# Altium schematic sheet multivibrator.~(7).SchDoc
size 431 x 279 mm; SheetNumber: 1; SheetTotal: 1; ENG_APP_DATE: --/--/--; DSN_APP_DATE: --/--/--; CHK_APP_DATE: --/--/--
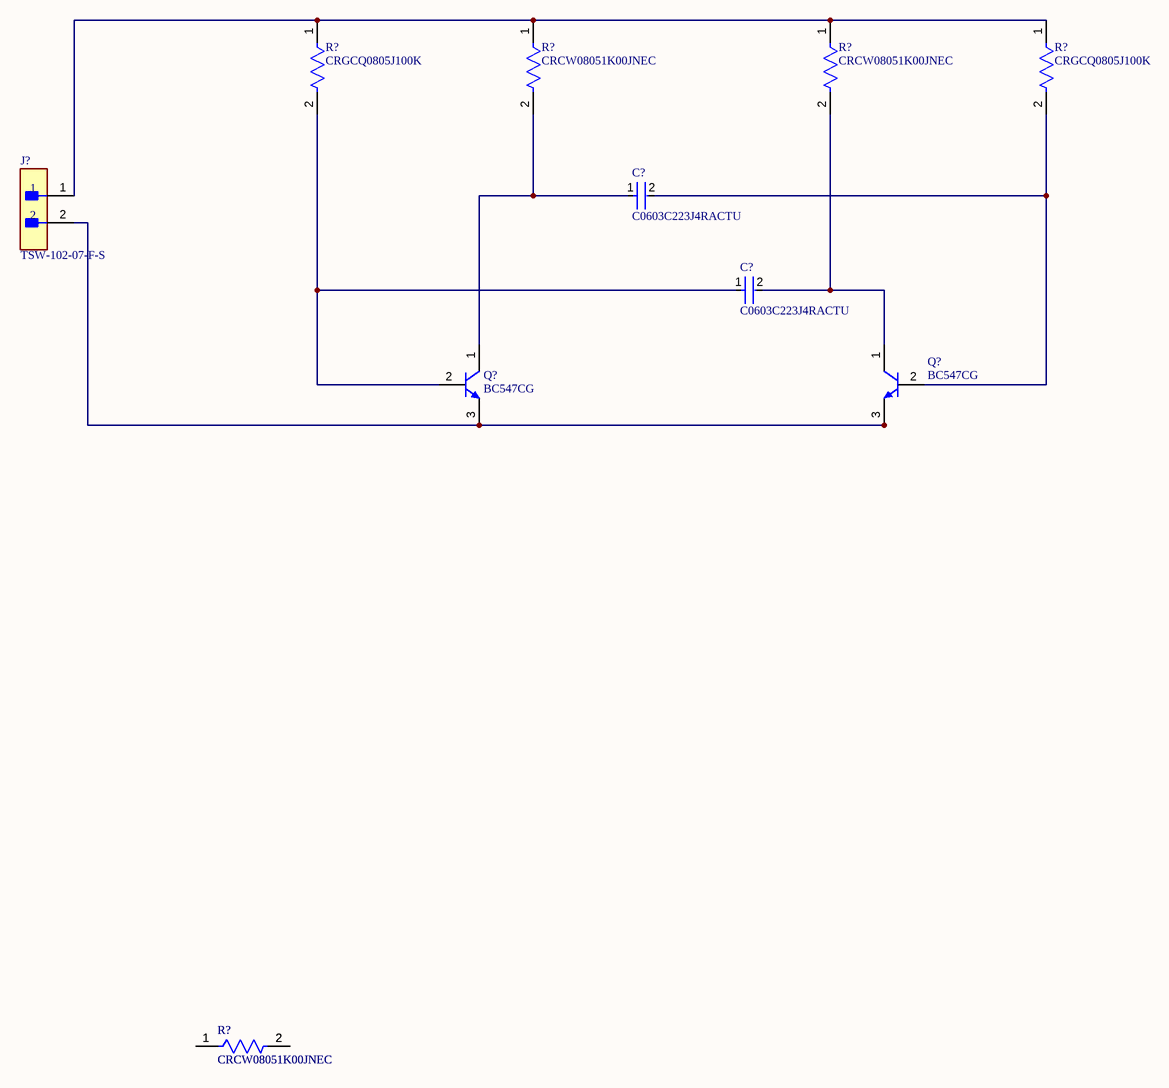
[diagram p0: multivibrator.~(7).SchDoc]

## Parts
(Parts that share a designator on the sheet are numbered #1, #2 ... from top to bottom, then left to right.)
C?#1  C0603C223J4RACTU  [FP-C0603C-CF-MFG]
C?#2  C0603C223J4RACTU  [FP-C0603C-CF-MFG]
J?  TSW-102-07-F-S  [FP-TSW-102-07-F-S-MFG]
Q?#1  BC547CG  [ONSC-TO-92-3-29-11]
Q?#2  BC547CG  [ONSC-TO-92-3-29-11]
R?#1  CRGCQ0805J100K  [FP-CRGCQ0805-IPC_C]
R?#2  CRCW08051K00JNEC  [FP-CRCW0805-e3-IPC_A]
R?#3  CRCW08051K00JNEC  [FP-CRCW0805-e3-IPC_A]
R?#4  CRGCQ0805J100K  [FP-CRGCQ0805-IPC_C]
R?#5  CRCW08051K00JNEC  [FP-CRCW0805-e3-IPC_A]
R?#6  CRCW08051K00JNEC  [FP-CRCW0805-e3-IPC_A]

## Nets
NetC?#1_1: C?#1.1 Q?#1.1(C) R?#2.2
NetC?#1_2: C?#1.2 Q?#2.2(B) R?#4.2
NetC?#2_1: C?#2.1 Q?#1.2(B) R?#1.2
NetC?#2_2: C?#2.2 Q?#2.1(C) R?#3.2
NetJ?_1: J?.1 R?#1.1 R?#2.1 R?#3.1 R?#4.1
NetJ?_2: J?.2 Q?#1.3(E) Q?#2.3(E)
NetR?#5_1: R?#5.1 R?#6.1
NetR?#5_2: R?#5.2 R?#6.2

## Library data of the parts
C?#1 C?#2 = CMP-2006-03745-2: CAP CER 0.022UF 16V 5% X7R 0603; Manufacturer: KEMET; Tolerance: 0.05; Automotive Grade: Grade 1; Temperature Coefficient: 30ppm/°C; Capacitance: 22,000 pF; Material: Ceramic; Value: 22,000 pF
J? = CMP-02766-001458-1: CONN HEADER VERT 2POS 2.54MM; Gender: Male; Max Current Rating: 7.6A; Number of Contacts: 2; Max Voltage Rating (AC): 550V
Q?#1 Q?#2 = CMP-1048-01464-1: Amplifier Transistor, NPN Silicon, 3-Pin TO-92, Pb-Free, Bulk Box; Manufacturer: On Semiconductor; IC Continuous (A): 0.1; fT Min (MHz): 150
R?#1 R?#4 = CMP-03211-009742-1: CRGCQ0805 100KΩ 0.125W ±100ppm/°C 5% 150V; Manufacturer: TE Connectivity; Tolerance: 0.05
R?#2 R?#3 R?#5 R?#6 = CMP-02407-005778-1: RES Thick Film, 1kΩ, 5%, 0.125W, 200ppm/°C, 0805; Max Power Dissipation: 125mW; Resistance: 1kR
